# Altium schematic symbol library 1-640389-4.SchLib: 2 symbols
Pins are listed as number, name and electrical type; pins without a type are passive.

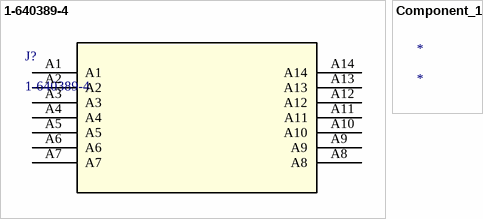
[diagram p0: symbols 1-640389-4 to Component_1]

## 1-640389-4
designator J?
No Description Available; Mfr_Name: TE Connectivity
footprint 1-640389-4_TYC
pins: A1, A2, A3, A4, A5, A6, A7, A8, A9, A10, A11, A12, A13, A14

## Component_1
designator *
